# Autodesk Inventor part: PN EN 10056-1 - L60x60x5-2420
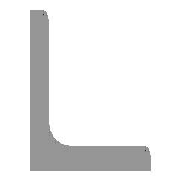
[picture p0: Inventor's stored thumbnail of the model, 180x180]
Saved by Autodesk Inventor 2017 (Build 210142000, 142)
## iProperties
IsCustomPart: 1
Created: 2016-02
Part Number: PN EN 10056-1 - L60x60x5-2420
Material: Stal, miękka
Description: Kątownik równoramienny
Document SubType Name: Modeling
Standard: PN
Designer: X
Standards Organization: PN
Language: pl-PL
Size Designation: L60x60x5
Categories: <MemberInstance><Categories><Category DisplayName="Kształtowniki konstrukcyjne" InternalName="089c4875-fa83-4c05-b084-43b9cc11f5ed" Mnemonic="GRDR"><CategoryPar
Stock Number: L60x60x5
Density: 7.85 g/cm^3
Appearance: Częściowo polerowana
_CCFamilyMember: 130
_CCFamilyDisplayName: PN EN 10056-1 (Kątownik równoramienny) - Kątownik równoramienny
_FrameMemberDoc: Frame Member File
_Version: 15.0.0
_GetPNFromCC: 1
G_W: 60,000 mm
G_H: 60,000 mm
G_L: 2420,000 mm
Author: X
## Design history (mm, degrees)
node "Płaszczyzna początkowa"
node "Płaszczyzna końcowa"
sketch "Szkic"
  geometry: L1 (-11.517, -3.517)-(-11.517, 39.483); L2 (-16.517, 43.483)-(-15.517, 43.483); L3 (-16.517, -16.517)-(-16.517, 43.483); L4 (-16.517, -16.517)-(43.483, -16.517); L5 (43.483, -15.517)-(43.483, -16.517); L6 (-3.517, -11.517)-(39.483, -11.517); L7 (0, 56.477)-(0, -28.683) reference; L8 (-28.683, 0)-(56.477, 0) reference; A1 r 8 centre (-3.517, -3.517) between (-11.517, -3.517) and (-3.517, -11.517); A2 r 4 centre (-15.517, 39.483) between (-11.517, 39.483) and (-15.517, 43.483); A3 r 4 centre (39.483, -15.517) between (43.483, -15.517) and (39.483, -11.517); 3 further points
  constraints: 12 end point, 6 point on circle, 6 point on line, 6 tangent, 3 centre point, 3 horizontal, 3 vertical, 1 equal radius
  dimensions: "d4" = 60 distance of L3.start L4.end (= b); "d6" = 60 distance of L3.start L2.start (= b); "d8" = 5 distance of point (43.483, -11.517) L4.end (= ParT); "d10" = 5 distance of L2.start point (-11.517, 43.483) (= ParT); "d17" = 8 radius of A1 (= R); "d18" = 4 radius of A2 (= R1); "d19" = 16.51748 distance between parallel lines of L8 L4 (= ex); "d20" = 16.51748 distance between parallel lines of L3 L7 (= d19)
extrude "Bryła" new body sketch "Szkic" stored distance "d11" = 2420 (= G_L); taper "d12" = 0 deg
node "Driven Length"
  sketch "Sketch3"
    geometry: L1 (0, 0)-(10, 0) reference
    constraints: 2 end point, 1 horizontal
  workplane "Work Plane10"
  sketch "Sketch4"
    geometry: L1 (-2, -60)-(12, -60) reference; L2 (-2, 2360)-(12, 2360) reference
    dimensions: "d24" = 2420 distance between parallel lines of L1 L2 (derived)
body "Solid1"
other parameters: "b" = 60 [user parameter; used in 3 equation terms], "ParT" = 5 [user parameter; used in 3 equation terms], "R" = 8 [user parameter; used in 1 equation term], "R1" = 4 [user parameter; used in 1 equation term], "G_L" = 2420 (= d24) [user parameter; used in 1 equation term], "d7" = 4 (derived), "d9" = 4 (derived), "ex" = 16.51748 (computed from b, ParT) [user parameter; used in 1 equation term], "d23" = 90 deg
